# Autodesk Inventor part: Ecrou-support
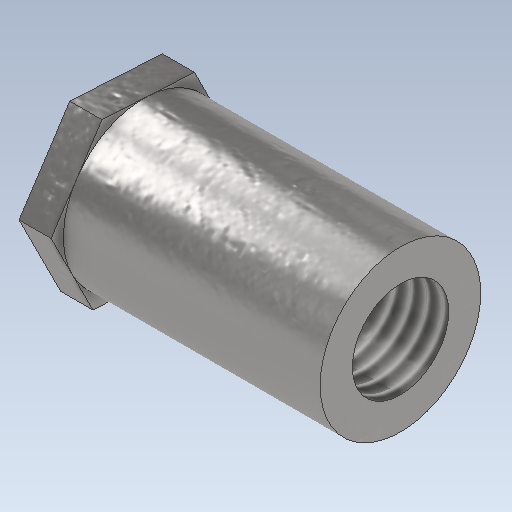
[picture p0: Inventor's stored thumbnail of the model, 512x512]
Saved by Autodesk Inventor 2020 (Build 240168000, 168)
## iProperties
Created: 2021-10
Part Number: Ecrou-support
Material: Générique
Document SubType Name: Modeling
Designer: bruno
Density: 1 g/cm^3
Appearance: Galvanisé
Mass: 0.115113 g
Surface Area: 2.56971 cm^2
Volume: 0.115113 cm^3
Author: bruno
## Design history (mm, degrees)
sketch "Esquisse1"
  geometry: L1 (-2.577, -1.3)-(-2.415, 1.582); L2 (-2.415, 1.582)-(0.163, 2.882); L3 (0.163, 2.882)-(2.577, 1.3); L4 (2.577, 1.3)-(2.415, -1.582); L5 (2.415, -1.582)-(-0.163, -2.882); L6 (-0.163, -2.882)-(-2.577, -1.3); 2 further points
  constraints: 12 end point, 1 coincident, 13 other
  dimensions: "d0" = 5 distance between parallel lines of L5 L2
extrude "Extrusion1" new body sketch "Esquisse1" distance "d1" = 1; taper "d2" = 0 deg
sketch "Esquisse2"
  geometry: L1 (1.582, 2.415)-(-1.3, 2.577) reference; C1 r 2.5 at (0, 0); 1 further point
  constraints: 1 centre point, 1 coincident, 1 tangent
extrude "Extrusion2" join sketch "Esquisse2" distance "d3" = 8; taper "d4" = 0 deg
sketch "Esquisse3"
  geometry: C1 r 1.5 at (0.003, 0.002); 1 further point
  constraints: 1 centre point
  dimensions: "d5" = 3 diameter of C1
extrude "Extrusion3" cut sketch "Esquisse3" distance "d6" = 15; taper "d7" = 0 deg
feature "Filetage1" dims "d8" = 10, "d9" = 0
node "Solide1"
